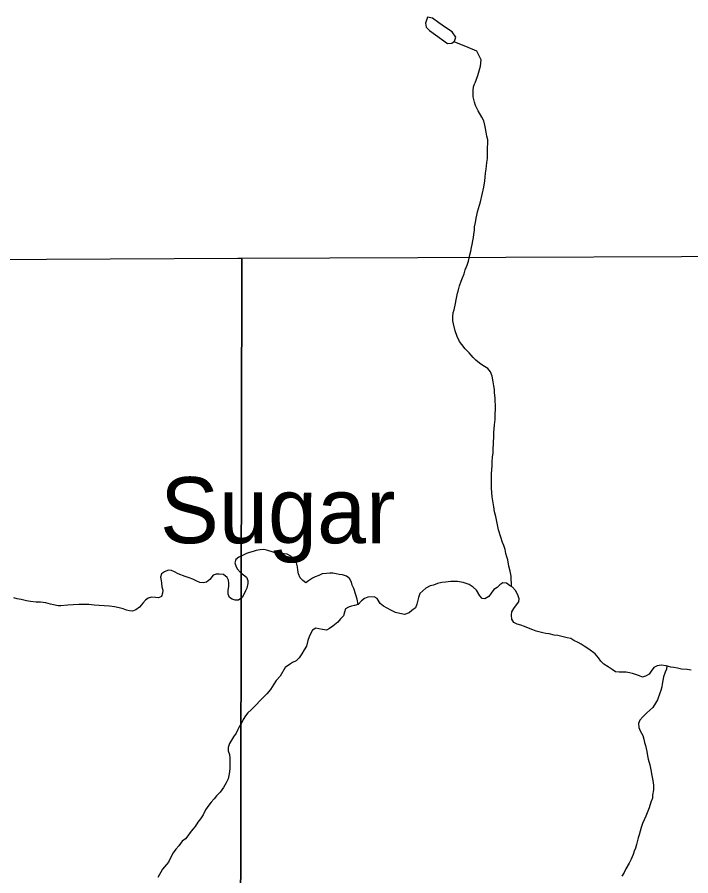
# Model space of a CAD drawing. Extents: x -21.1 to 50.3, y -4.9 to 22.1.
# Drawn here: x -16.576 to -15.609, y 20.75 to 21.981 of the extents above; entities that cross this region are included whole.
import ezdxf

# ---------------------------------------------------------------- set-up
doc = ezdxf.new("R2010")
doc.units = 0
for name, color, linetype in [('GM_X_Minor_Lake', 7, 'Continuous'), ('GM_X_Minor_River', 7, 'Continuous'), ('GM_X_Minor_River_Text', 7, 'Continuous'), ('GM_X_Section', 7, 'Continuous')]:
    doc.layers.add(name, color=color, linetype=linetype)

msp = doc.modelspace()

# ---------------------------------------------------------------- linework, layer by layer
at = {"layer": 'GM_X_Minor_Lake'}
for points in [[(-15.9581, 21.9434), (-15.952, 21.9438), (-15.9483, 21.9468), (-15.9464, 21.9525), (-15.9514, 21.9601), (-15.9609, 21.9665), (-15.9708, 21.9732), (-15.9799, 21.9796), (-15.9871, 21.9811), (-15.9897, 21.9724), (-15.9889, 21.967), (-15.9843, 21.9621)], [(-15.9843, 21.9621), (-15.9581, 21.9434)]]:
    msp.add_lwpolyline(points, dxfattribs=at)
at = {"layer": 'GM_X_Minor_River'}
for points in [[(-15.949, 21.9463), (-15.9289, 21.9382), (-15.9168, 21.933), (-15.9103, 21.9202), (-15.9113, 21.9103), (-15.915, 21.897), (-15.9191, 21.8864)], [(-15.9008, 21.7883), (-15.9008, 21.7936), (-15.9005, 21.8005), (-15.9006, 21.8054), (-15.9017, 21.8107), (-15.9026, 21.8164), (-15.9037, 21.8217), (-15.9046, 21.8262), (-15.9061, 21.8327), (-15.9088, 21.8376), (-15.9142, 21.8466), (-15.9181, 21.8546), (-15.9197, 21.8591), (-15.9213, 21.8667), (-15.9214, 21.8758), (-15.921, 21.8811), (-15.9191, 21.8864)], [(-15.8666, 21.1648), (-15.8669, 21.1797), (-15.8681, 21.1869), (-15.8701, 21.194), (-15.8717, 21.2028), (-15.8732, 21.2073), (-15.8744, 21.2122), (-15.8756, 21.2179), (-15.8772, 21.2236), (-15.8791, 21.2281), (-15.8819, 21.2353), (-15.885, 21.2459), (-15.8866, 21.2531), (-15.889, 21.2652), (-15.8906, 21.2716), (-15.8918, 21.2788), (-15.8942, 21.2932), (-15.8946, 21.2997), (-15.8951, 21.3057), (-15.8952, 21.3164), (-15.8949, 21.3221), (-15.8949, 21.3266), (-15.8946, 21.3319), (-15.8943, 21.3384), (-15.8943, 21.3433), (-15.8936, 21.3502), (-15.8929, 21.3566), (-15.8926, 21.3627), (-15.8923, 21.3688), (-15.8924, 21.3733), (-15.892, 21.3775), (-15.8917, 21.382), (-15.8917, 21.3862), (-15.8914, 21.3904), (-15.8907, 21.3968), (-15.89, 21.4041), (-15.8897, 21.412), (-15.8894, 21.4189), (-15.8895, 21.4249), (-15.8899, 21.4306), (-15.89, 21.4348), (-15.8908, 21.4431), (-15.8908, 21.4473), (-15.8917, 21.4526), (-15.8925, 21.4583), (-15.8941, 21.4663), (-15.8964, 21.4727), (-15.9002, 21.4772), (-15.9075, 21.4817), (-15.9121, 21.4851), (-15.9174, 21.4892), (-15.9216, 21.4929), (-15.9274, 21.4997), (-15.9331, 21.5057), (-15.9377, 21.5118), (-15.9408, 21.5159), (-15.9443, 21.5231), (-15.9474, 21.5314), (-15.9498, 21.5413), (-15.9506, 21.5458), (-15.9506, 21.5515), (-15.9499, 21.5576), (-15.9488, 21.5617), (-15.947, 21.5705), (-15.946, 21.5758), (-15.9449, 21.5808), (-15.9438, 21.5853), (-15.9423, 21.5903), (-15.9409, 21.596), (-15.9386, 21.6024), (-15.9368, 21.6074), (-15.9342, 21.6131), (-15.9328, 21.6188), (-15.9302, 21.6257), (-15.9283, 21.6314), (-15.9272, 21.6355), (-15.9262, 21.6405), (-15.9247, 21.6458), (-15.9236, 21.6508), (-15.9229, 21.6553), (-15.9218, 21.6606), (-15.9211, 21.6652), (-15.9204, 21.6694), (-15.9197, 21.6758), (-15.9194, 21.6804), (-15.9183, 21.6869), (-15.9172, 21.6929), (-15.9161, 21.6971), (-15.915, 21.7021), (-15.9136, 21.707), (-15.9125, 21.7116), (-15.911, 21.7161), (-15.9059, 21.7374), (-15.9049, 21.7462), (-15.9042, 21.7519), (-15.9039, 21.7576), (-15.9028, 21.7633), (-15.9024, 21.7678), (-15.9017, 21.7727), (-15.901, 21.7784), (-15.9008, 21.7883)], [(-16.0865, 21.1392), (-16.0879, 21.1466), (-16.0898, 21.153), (-16.0929, 21.1617), (-16.0949, 21.1666), (-16.0961, 21.1708), (-16.0988, 21.1761), (-16.1033, 21.1794), (-16.1091, 21.1813), (-16.1136, 21.182), (-16.1178, 21.1831), (-16.1227, 21.1838), (-16.1269, 21.1838), (-16.1318, 21.1833), (-16.1382, 21.1829), (-16.1428, 21.1806), (-16.1481, 21.1786), (-16.1522, 21.1767), (-16.1575, 21.1729), (-16.1616, 21.1698), (-16.1658, 21.1732), (-16.1696, 21.1773), (-16.172, 21.183), (-16.1732, 21.1883), (-16.1736, 21.1928), (-16.1748, 21.1985), (-16.1783, 21.2042), (-16.1832, 21.2083), (-16.1882, 21.2109), (-16.1927, 21.2116), (-16.1969, 21.212), (-16.2014, 21.2112), (-16.2083, 21.2138), (-16.2159, 21.2164), (-16.2216, 21.2178), (-16.2273, 21.2174), (-16.2326, 21.2162), (-16.2371, 21.215), (-16.2424, 21.2135), (-16.2469, 21.2119), (-16.2522, 21.2092), (-16.2575, 21.2069), (-16.262, 21.2034), (-16.2635, 21.1985), (-16.2619, 21.1943), (-16.26, 21.1902), (-16.255, 21.1845), (-16.2508, 21.1815), (-16.2466, 21.1781), (-16.2446, 21.1732), (-16.245, 21.169), (-16.2464, 21.1626), (-16.2479, 21.1584), (-16.2505, 21.1531), (-16.2527, 21.1489), (-16.2584, 21.1454), (-16.2629, 21.1454), (-16.2671, 21.1465), (-16.2713, 21.1491), (-16.2729, 21.1536), (-16.2729, 21.1593), (-16.2722, 21.165), (-16.2719, 21.1696), (-16.2727, 21.1737), (-16.2746, 21.1779), (-16.2796, 21.182), (-16.286, 21.1823), (-16.2902, 21.1823), (-16.2947, 21.1811), (-16.2992, 21.1746), (-16.3041, 21.1708), (-16.309, 21.17), (-16.3136, 21.1707), (-16.3178, 21.1722), (-16.3235, 21.1752), (-16.3288, 21.1774), (-16.3349, 21.1792), (-16.3448, 21.183), (-16.3501, 21.1859), (-16.3543, 21.1878), (-16.3592, 21.1881), (-16.3645, 21.1858), (-16.3686, 21.1827), (-16.3701, 21.1782), (-16.3689, 21.1736), (-16.3685, 21.1695), (-16.3681, 21.1645), (-16.3669, 21.1596), (-16.3672, 21.1551), (-16.3687, 21.1505), (-16.3732, 21.1485), (-16.3774, 21.1489), (-16.3831, 21.1496), (-16.3876, 21.148), (-16.3917, 21.145), (-16.3955, 21.1408), (-16.4, 21.135), (-16.4056, 21.1312), (-16.4102, 21.1296), (-16.4147, 21.13), (-16.4189, 21.1307)], [(-15.9045, 21.1471), (-15.9086, 21.1474), (-15.9117, 21.1516), (-15.9167, 21.1595), (-15.9213, 21.164), (-15.927, 21.1677), (-15.9358, 21.1703), (-15.9437, 21.1718), (-15.9487, 21.1721), (-15.9536, 21.172), (-15.9612, 21.1712), (-15.9665, 21.1704), (-15.9725, 21.1692), (-15.9782, 21.1669), (-15.9831, 21.1657), (-15.9895, 21.1626), (-15.9936, 21.1584), (-15.9981, 21.1546), (-16, 21.1492), (-16.0014, 21.1435), (-16.0025, 21.1394), (-16.0044, 21.134), (-16.0093, 21.1302), (-16.0134, 21.1271), (-16.0198, 21.1248), (-16.0266, 21.1259), (-16.0327, 21.1277), (-16.0396, 21.1307), (-16.0449, 21.1337), (-16.0499, 21.1367), (-16.0548, 21.1404), (-16.0594, 21.1476), (-16.0636, 21.1498), (-16.0724, 21.1494), (-16.0773, 21.1478), (-16.0818, 21.144), (-16.0866, 21.139), (-16.0916, 21.1374), (-16.0961, 21.1366), (-16.1002, 21.1351), (-16.1044, 21.1328), (-16.1059, 21.1282), (-16.1073, 21.1229), (-16.1118, 21.1186), (-16.1156, 21.1137), (-16.1227, 21.1079), (-16.1276, 21.1045), (-16.1317, 21.1022), (-16.1374, 21.1029), (-16.1428, 21.1043), (-16.1473, 21.105), (-16.1518, 21.1023), (-16.1544, 21.0978), (-16.157, 21.0928), (-16.1589, 21.0875), (-16.1607, 21.0791), (-16.1637, 21.0742), (-16.1674, 21.0681), (-16.1711, 21.0627), (-16.1756, 21.0581), (-16.1809, 21.0558), (-16.1851, 21.0531), (-16.1911, 21.0485), (-16.1985, 21.0363), (-16.2041, 21.0298), (-16.2075, 21.0248), (-16.2123, 21.0172), (-16.2176, 21.0107), (-16.2225, 21.0061), (-16.2273, 21.0011), (-16.2326, 20.995), (-16.2401, 20.9877), (-16.2446, 20.9835), (-16.248, 20.9793), (-16.2513, 20.974), (-16.2543, 20.9679), (-16.2573, 20.9637), (-16.2591, 20.9595), (-16.2617, 20.9545), (-16.2655, 20.9492), (-16.2684, 20.9446), (-16.2711, 20.9396), (-16.2729, 20.9339), (-16.2728, 20.929), (-16.2713, 20.9237), (-16.2708, 20.9188), (-16.2708, 20.9146), (-16.2704, 20.9089), (-16.2707, 20.9032), (-16.2714, 20.896), (-16.2732, 20.8892), (-16.2758, 20.8834), (-16.2795, 20.8766), (-16.2844, 20.8697), (-16.2896, 20.8647), (-16.293, 20.8605), (-16.2975, 20.8556), (-16.3005, 20.8514), (-16.3053, 20.8445), (-16.3087, 20.8376), (-16.3128, 20.8315)], [(-15.6086, 21.045), (-15.6143, 21.0457), (-15.6226, 21.0464), (-15.6283, 21.0475), (-15.6337, 21.0486), (-15.6378, 21.0493), (-15.6447, 21.0511), (-15.6515, 21.0518), (-15.6576, 21.051), (-15.6621, 21.0487), (-15.6658, 21.0434), (-15.6688, 21.0392), (-15.6741, 21.0361), (-15.6786, 21.0349), (-15.6828, 21.0368), (-15.687, 21.0382), (-15.6927, 21.0401), (-15.6969, 21.0408), (-15.7018, 21.0419), (-15.712, 21.0418), (-15.717, 21.0425), (-15.7219, 21.0459), (-15.7276, 21.0496), (-15.7337, 21.0534), (-15.7383, 21.0575), (-15.7418, 21.0624), (-15.7464, 21.0681), (-15.7556, 21.0748), (-15.762, 21.0793), (-15.7666, 21.0823), (-15.7708, 21.0845), (-15.7769, 21.0875), (-15.7815, 21.0901), (-15.7864, 21.0912), (-15.8001, 21.0945), (-15.8054, 21.0952), (-15.8122, 21.0967), (-15.8172, 21.0974), (-15.8214, 21.0981), (-15.8255, 21.0992), (-15.8312, 21.1007), (-15.8358, 21.1025), (-15.8419, 21.1051), (-15.848, 21.1074), (-15.8529, 21.1092), (-15.8582, 21.1107), (-15.8632, 21.1133), (-15.8659, 21.1178), (-15.8663, 21.1235), (-15.866, 21.1284), (-15.863, 21.133), (-15.8593, 21.1384), (-15.8559, 21.143), (-15.8556, 21.1471), (-15.8575, 21.1528), (-15.8606, 21.1592), (-15.8648, 21.1637), (-15.8694, 21.1664), (-15.8736, 21.1694), (-15.8789, 21.1701), (-15.8831, 21.1674), (-15.8872, 21.1635), (-15.8917, 21.1605), (-15.8958, 21.1551), (-15.8988, 21.1505), (-15.9045, 21.1471)], [(-16.4189, 21.1307), (-16.4238, 21.1329), (-16.4295, 21.1344), (-16.436, 21.1355), (-16.4432, 21.1365), (-16.4508, 21.1372), (-16.458, 21.1375), (-16.4652, 21.1382), (-16.4728, 21.1389), (-16.4804, 21.1392), (-16.4872, 21.1392), (-16.4955, 21.1383), (-16.5031, 21.1379), (-16.5129, 21.137), (-16.5171, 21.137), (-16.5235, 21.1385), (-16.5277, 21.1396), (-16.5346, 21.1414), (-16.5422, 21.1421), (-16.5486, 21.1424), (-16.5566, 21.1431), (-16.5626, 21.1442), (-16.5702, 21.146), (-16.5756, 21.1471), (-16.5805, 21.1486)], [(-15.6425, 21.0506), (-15.6435, 21.0504), (-15.6439, 21.0462), (-15.6457, 21.042), (-15.6483, 21.0352), (-15.6494, 21.0302), (-15.6501, 21.0249), (-15.6508, 21.0207), (-15.6523, 21.0158), (-15.6534, 21.0116), (-15.6571, 21.0025), (-15.6597, 20.9975), (-15.6638, 20.9914), (-15.6679, 20.9876), (-15.672, 20.9837), (-15.678, 20.978), (-15.6821, 20.973), (-15.684, 20.9685), (-15.6836, 20.9628), (-15.6816, 20.9578), (-15.6781, 20.9511), (-15.6766, 20.9461), (-15.6754, 20.9412), (-15.6742, 20.937), (-15.6722, 20.9283), (-15.6714, 20.9219), (-15.6702, 20.9174), (-15.6679, 20.909), (-15.6666, 20.9018), (-15.665, 20.8939), (-15.6635, 20.8867), (-15.6626, 20.8799), (-15.6626, 20.873), (-15.664, 20.8654), (-15.6643, 20.8613), (-15.6666, 20.8555), (-15.6691, 20.8472), (-15.6735, 20.8354), (-15.6784, 20.8251), (-15.6802, 20.8194), (-15.6831, 20.8087), (-15.6846, 20.8045), (-15.6857, 20.8004), (-15.6872, 20.7947), (-15.6886, 20.7897), (-15.6905, 20.7851), (-15.6919, 20.7806), (-15.6945, 20.7737), (-15.6975, 20.768), (-15.7023, 20.76), (-15.7049, 20.7547), (-15.7079, 20.7493)], [(-16.3128, 20.8315), (-16.3165, 20.8269), (-16.3202, 20.8208), (-16.3236, 20.8166), (-16.3274, 20.812), (-16.3311, 20.8074), (-16.3341, 20.8029), (-16.339, 20.7994), (-16.3438, 20.7929), (-16.348, 20.7883), (-16.3521, 20.783), (-16.3554, 20.7769), (-16.3584, 20.7696), (-16.367, 20.7593), (-16.3741, 20.7475)]]:
    msp.add_lwpolyline(points, dxfattribs=at)
at = {"layer": 'GM_X_Section'}
for points in [[(-16.2592, 21.6354), (-16.2535, 21.6355), (-16.2553, 20.617), (-17.2821, 20.6195), (-17.2882, 21.6307), (-17.2662, 21.6301)], [(-15.2438, 21.6396), (-15.2347, 21.6397), (-15.2312, 20.6195), (-16.2553, 20.617), (-16.2535, 21.6355)]]:
    msp.add_lwpolyline(points, close=True, dxfattribs=at)

# ---------------------------------------------------------------- texts
at = {"layer": 'GM_X_Minor_River_Text'}
msp.add_text('Sugar', height=0.09471, rotation=359.9766, dxfattribs=at).set_placement((-16.3708, 21.2269))

doc.saveas('drawing.dxf')
